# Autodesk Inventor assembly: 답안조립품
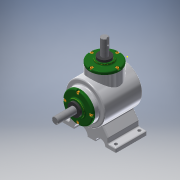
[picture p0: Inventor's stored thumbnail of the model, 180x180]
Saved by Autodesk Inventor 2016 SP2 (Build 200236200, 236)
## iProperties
Created: 2018-08
Part Number: 답안조립품
Document SubType Name: Assembly
Designer: Administrator
Author: Administrator
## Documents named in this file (14)
- Z:\ATC마스터자격증시험\480807V1001 오기수(인벤터)\480807V1001\답안조립품.iam
- Z:\ATC마스터자격증시험\480807V1001 오기수(인벤터)\480807V1001\메인 베벨기어.ipt
- Z:\ATC마스터자격증시험\480807V1001 오기수(인벤터)\480807V1001\메인 축.ipt
- 메인 축.ipt
- Z:\ATC마스터자격증시험\480807V1001 오기수(인벤터)\480807V1001\베어링 6203.ipt
- Z:\ATC마스터자격증시험\480807V1001 오기수(인벤터)\480807V1001\본체.ipt
- Z:\ATC마스터자격증시험\480807V1001 오기수(인벤터)\480807V1001\볼트 M4.ipt
- Z:\ATC마스터자격증시험\480807V1001 오기수(인벤터)\480807V1001\서브 베벨기어.ipt
- Z:\ATC마스터자격증시험\480807V1001 오기수(인벤터)\480807V1001\서브 축.ipt
- 서브 축.ipt
- Z:\ATC마스터자격증시험\480807V1001 오기수(인벤터)\480807V1001\오일실 17 32 8.ipt
- Z:\ATC마스터자격증시험\480807V1001 오기수(인벤터)\480807V1001\커버.ipt
- Z:\ATC마스터자격증시험\480807V1001 오기수(인벤터)\480807V1001\키 4x4.ipt
- Z:\ATC마스터자격증시험\480807V1001 오기수(인벤터)\480807V1001\키 5x5.ipt
